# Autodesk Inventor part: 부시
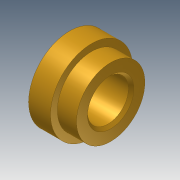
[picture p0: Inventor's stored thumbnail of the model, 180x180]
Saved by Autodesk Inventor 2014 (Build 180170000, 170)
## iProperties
Company: 한국ATC센터
Created: 2014-08
Part Number: 부시
Document SubType Name: Modeling
Designer: KYOUNG IL JANG
Density: 1 g/cm^3
Checked By: KYOUNG IL JANG
Material: 일반
Appearance: 황동 - 새틴
Mass: 6.39105 g
Surface Area: 30.183 cm^2
Volume: 6.39105 cm^3
Author: KYOUNG IL JANG
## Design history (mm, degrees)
sketch "스케치1"
  geometry: L1 (0, 0)-(15, 0); L2 (0, 7.5)-(15, 7.5); L3 (15, 7.5)-(15, 12.5); L4 (15, 12.5)-(8, 12.5); L5 (8, 12.5)-(8, 15); L6 (8, 15)-(0, 15); L7 (0, 15)-(0, 7.5)
  constraints: 14 end point, 4 parallel, 2 vertical alignment, 1 horizontal, 1 perpendicular, 1 vertical
  dimensions: "d0" = 15 distance of L1.start L1.end; "d1" = 15 diameter of L2 L1; "d2" = 25 diameter of L4 L1; "d3" = 8 distance of L5.end L6.end; "d4" = 30 diameter of L6 L1
revolve "회전1" sketch "스케치1" stored, may be unused: angle "d5" = 90 deg
chamfer "모따기1" distance "d6" = 1; stored, may be unused: second distance "d7" = 2, angle "d8" = 45 deg
node "솔리드1"
